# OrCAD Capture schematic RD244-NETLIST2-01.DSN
size A3
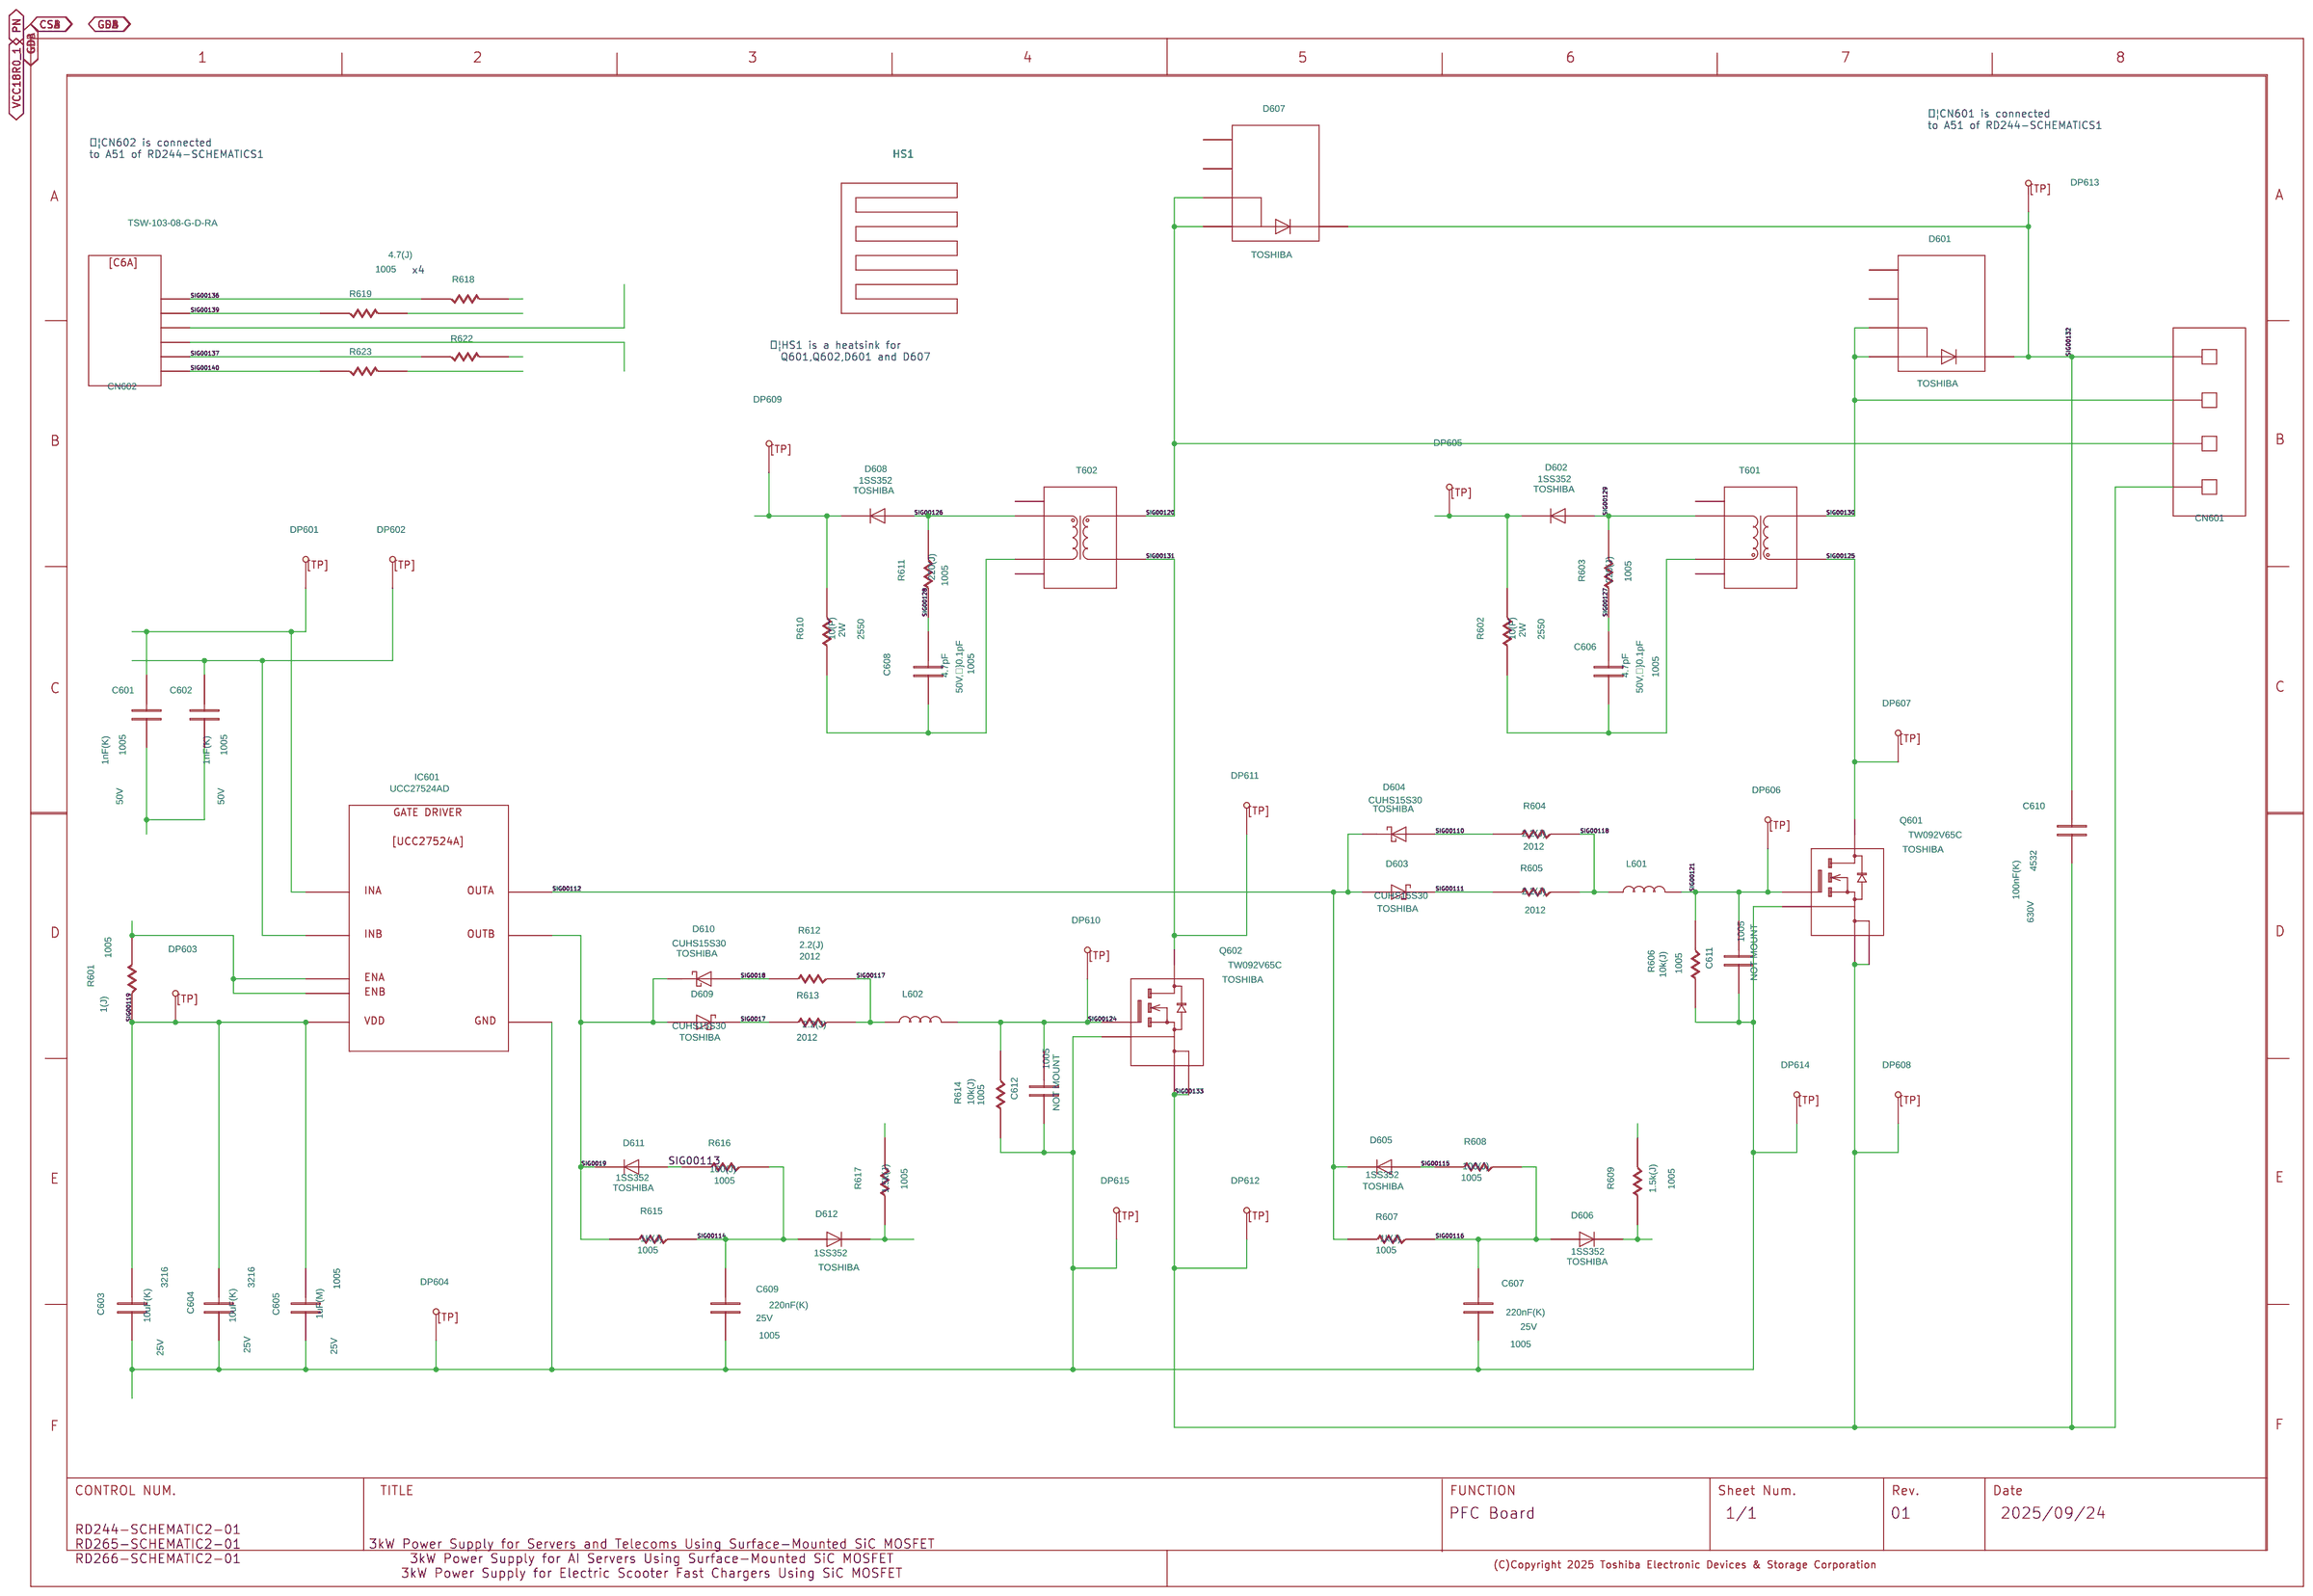
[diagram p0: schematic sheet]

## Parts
C601  C
C602  C
C603  C
C604  C
C605  C
C606  C
C607  C
C608  C
C609  C
C610  C
C611  C
C612  C
CN601  RD-244_CN_FROM_PFC
CN602  C6A
D601  TRS12V65H
D602  D
D603  CUHS15S30
D604  CUHS15S30
D605  D
D606  D
D607  TRS12V65H
D608  D
D609  CUHS15S30
D610  CUHS15S30
D611  D
D612  D
DP601  TP
DP602  TP
DP603  TP
DP604  TP
DP605  TP
DP606  TP
DP607  TP
DP608  TP
DP609  TP
DP610  TP
DP611  TP
DP612  TP
DP613  TP
DP614  TP
DP615  TP
HS1  UB4060-12BM-1GG
IC601  L27524
L601  L
L602  L
Q601  NCHMOSFET_DFN8X8-02
Q602  NCHMOSFET_DFN8X8-02
R601  R
R602  R
R603  R
R604  R
R605  R
R606  R
R607  R
R608  R
R609  R
R610  R
R611  R
R612  R
R613  R
R614  R
R615  R
R616  R
R617  R
R618  R
R619  R
R622  R
R623  R
T601  PH9505_100NLT
T602  PH9505_100NLT
U?#1  WAKU_DEF100

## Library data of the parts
C601 C602 = C: CHIPSIZE: 1005; COMP: PRT_52; COMPONENTTYPE: 4; GCOUNT: 1; MAXGCOUNT: 1; SAVECOUNT: 0; SIZECODESMD: 1005; VAL1: 1nF(K); VAL2: 50V; VAL3: GRM155R71H102KA01
C603 C604 = C: CHIPSIZE: 3216; COMP: PRT_46; COMPONENTTYPE: 4; GCOUNT: 1; MAXGCOUNT: 1; SAVECOUNT: 0; SIZECODESMD: 3216; VAL1: 10uF(K); VAL2: 25V; VAL3: GRM31CR71E106KA12
C605 = C: CHIPSIZE: 1005; COMP: PRT_52; COMPONENTTYPE: 4; GCOUNT: 1; MAXGCOUNT: 1; SAVECOUNT: 0; SIZECODESMD: 1005; VAL1: 1uF(M); VAL2: 25V; VAL3: GRM155C81E105ME11
C606 C608 = C: CHIPSIZE: 1005; COMP: PRT_52; COMPONENTTYPE: 4; GCOUNT: 1; MAXGCOUNT: 1; SAVECOUNT: 0; SIZECODESMD: 1005; VAL1: 4.7pF; VAL2: 50V,}0.1pF; VAL3: GRM1555C1H4R7BA01D
C607 = C: CHIPSIZE: 1005; COMP: PRT_52; COMPONENTTYPE: 4; GCOUNT: 1; MAXGCOUNT: 1; SAVECOUNT: 0; SIZECODESMD: 1005; VAL1: 220nF(K); VAL2: 25V; VAL3: GRM155C81E224KE01
C609 = C: ADSCNVFLAG: ON; ADSCOMPONENTNAME: C_1005; CHIPSIZE: 1005; COMP: PRT_52; COMPONENTTYPE: 4; GCOUNT: 1; ICX_PART_MODEL: CON_47N; MAXGCOUNT: 1; SAVECOUNT: 0; SIZECODESMD: 1005; SQ_PART_MODEL: CON_47N; VAL1: 220nF(K); VAL2: 25V; VAL3: GRM155C81E224KE01
C610 = C: ADSCNVFLAG: ON; ADSCOMPONENTNAME: C_4532; COMP: K03S007Y; COMPONENTTYPE: 4; GCOUNT: 1; ICX_PART_MODEL: CON_100N; MAXGCOUNT: 1; SAVECOUNT: 0; SIZECODESMD: 4532; SQ_PART_MODEL: CON_100N; VAL1: 100nF(K); VAL2: 630V; VAL3: GRJ43DR72J104KWJ1K
C611 C612 = C: CHIPSIZE: 1005; COMP: PRT_52; COMPONENTTYPE: 4; GCOUNT: 1; MAXGCOUNT: 1; NOTMOUNT: NOT MOUNT; SAVECOUNT: 0; SIZECODESMD: 1005; VAL1: 1uF(M); VAL2: 25V; VAL3: GRM155C81E105ME11
CN601 = RD-244_CN_FROM_PFC: COMPONENTTYPE: 4
CN602 = C6A: ADSCNVFLAG: ON; COMP: K22S0030; COMPONENTTYPE: 4; GATENO: 1; GCOUNT: 1; MAXGCOUNT: 1; OUMEPARTTYPE2: CN; VAL3: TSW-103-08-G-D-RA
D601 D607 = TRS12V65H: COMPONENTTYPE: 4; GCOUNT: 1; MAXGCOUNT: 1; USERCOMPTEXT3: TOSHIBA
D602 D605 D606 D608 D611 = D: COMP: PRT_27; COMPONENTTYPE: 4; GCOUNT: 1; MAXGCOUNT: 1; USERCOMPTEXT2: 80V,0.1A; USERCOMPTEXT3: TOSHIBA; VAL1: 1SS352(TPH3,F); VAL3: 1SS352
D603 D604 D609 D610 = CUHS15S30: COMPONENTTYPE: 4; GCOUNT: 1; MAXGCOUNT: 1; USERCOMPTEXT2: 30V,1.5A; USERCOMPTEXT3: TOSHIBA
D612 = D: ADSCNVFLAG: ON; ADSCOMPONENTNAME: D_D; COMP: PRT_27; COMPONENTTYPE: 4; GCOUNT: 1; MAXGCOUNT: 1; USERCOMPTEXT2: 80V,0.1A; USERCOMPTEXT3: TOSHIBA; VAL1: 1SS352(TPH3,F); VAL3: 1SS352
DP601-DP615 = TP: COMP: DTP815; COMPONENTTYPE: 4; USERCOMPTEXT1: ƒ³1.5mm
HS1 = UB4060-12BM-1GG: COMPONENTTYPE: 4
IC601 = L27524: COMP: PRT_63; COMPONENTTYPE: 4; VAL3: UCC27524AD
L601 L602 = L: COMP: PRT_30; COMPONENTTYPE: 4; SAVECOUNT: 0; VAL3: LSMCC321611T800RG
Q601 Q602 = NCHMOSFET_DFN8X8-02: COMPONENTTYPE: 4; USERCOMPTEXT3: TOSHIBA; VAL3: TW092V65C
R601 = R: CHIPSIZE: 1608; COMP: GDM010004481; COMPONENTTYPE: 4; GCOUNT: 1; MAXGCOUNT: 1; SAVECOUNT: 0; SIZECODESMD: 1005; VAL1: 1(J); VAL2: 63mW; VAL3: RK73B1ETTP1R0J
R602 R610 = R: ADSCNVFLAG: ON; ADSCOMPONENTNAME: R_2550; COMP: K01S003U; COMPONENTTYPE: 4; GCOUNT: 1; ICX_PART_MODEL: RES_750; MAXGCOUNT: 1; SAVECOUNT: 0; SIZECODESMD: 2550; SQ_PART_MODEL: RES_750; USERCOMPTEXT1: 10(F); VAL1: 10(F); VAL2: 2W; VAL3: WK73R2H2TTE7500F
R603 R611 = R: CHIPSIZE: 1608; COMP: GDM010004481; COMPONENTTYPE: 4; GCOUNT: 1; MAXGCOUNT: 1; SAVECOUNT: 0; SIZECODESMD: 1005; VAL1: 220(J); VAL2: 63mW; VAL3: RK73B1ETTP221J
R604 R605 R612 R613 = R: CHIPSIZE: 3216; COMP: R2012; COMPONENTTYPE: 4; GCOUNT: 1; MAXGCOUNT: 1; SAVECOUNT: 0; SIZECODESMD: 2012; VAL1: 2.2(J); VAL2: 250mW; VAL3: RK73B2ATTD2R2J
R606 R614 = R: CHIPSIZE: 1608; COMP: GDM010004481; COMPONENTTYPE: 4; GCOUNT: 1; MAXGCOUNT: 1; SAVECOUNT: 0; SIZECODESMD: 1005; VAL1: 10k(J); VAL2: 63mW; VAL3: RK73B1ETTP103J
R607 = R: ADSCNVFLAG: ON; ADSCOMPONENTNAME: R_1608; CHIPSIZE: 1608; COMP: GDM010004481; COMPONENTTYPE: 4; GCOUNT: 1; ICX_PART_MODEL: RES_1.74K; MAXGCOUNT: 1; SAVECOUNT: 0; SIZECODESMD: 1005; SQ_PART_MODEL: RES_1.74K; VAL1: 1k(J); VAL2: 63mW; VAL3: RK73B1ETTP102J
R608 R616 = R: CHIPSIZE: 1608; COMP: GDM010004481; COMPONENTTYPE: 4; GCOUNT: 1; MAXGCOUNT: 1; SAVECOUNT: 0; SIZECODESMD: 1005; VAL1: 100(J); VAL2: 63mW; VAL3: RK73B1ETTP101J
R609 R617 = R: CHIPSIZE: 1608; COMP: GDM010004481; COMPONENTTYPE: 4; GCOUNT: 1; MAXGCOUNT: 1; SAVECOUNT: 0; SIZECODESMD: 1005; VAL1: 1.5k(J); VAL2: 63mW; VAL3: RK73B1ETTP152J
R615 = R: CHIPSIZE: 1608; COMP: GDM010004481; COMPONENTTYPE: 4; GCOUNT: 1; MAXGCOUNT: 1; SAVECOUNT: 0; SIZECODESMD: 1005; VAL1: 1K(J); VAL2: 63mW; VAL3: RK73B1ETTP102J
R618 = R: CHIPSIZE: 1608; COMP: GDM010004481; COMPONENTTYPE: 4; GCOUNT: 1; MAXGCOUNT: 1; SAVECOUNT: 0; SIZECODESMD: 1005; VAL1: 4.7(J); VAL2: 63mW; VAL3: RK73B1ETTP4R7J
R619 = R: CHIPSIZE: 1608; COMP: GDM010004481; COMPONENTTYPE: 4; GCOUNT: 1; MAXGCOUNT: 1; SAVECOUNT: 0; SIZECODESMD: 1005; VAL1: 4.7; VAL2: 63mW; VAL3: RK73B1ETTP4R7J
R622 R623 = R: CHIPSIZE: 1608; COMP: GDM010004481; COMPONENTTYPE: 4; GCOUNT: 1; MAXGCOUNT: 1; SAVECOUNT: 0; SIZECODESMD: 1005; VAL1: 0; VAL2: 63mW; VAL3: RK73Z1ETTP
T601 T602 = PH9505_100NLT: COMPONENTTYPE: 4; GCOUNT: 1; MAXGCOUNT: 1
U?#1 = WAKU_DEF100: COMPONENTTYPE: 2; DATE: 2025/09/24; DESIGNED: TOSHIBA; DRAWINGNUMBER: RD244-SCHEMATIC2-01 / RD265-SCHEMATIC2-01 / RD266-SCHEMATIC2-01; FUNCTION: PFC Board; PAGENUMBER: 2; REVISION: 01; SAVECOUNT: 3; SHEETNUMBER: 1/1; SHTSAVECOUNT: 186; TITLE: 3kW Power Supply for Servers and Telecoms Using Surface-Mounted SiC MOSFET / 3kW Power Supply for AI Servers Using Surface-Mounted SiC MOSFET / 3kW Power Supply for Electric Scooter Fast Chargers Using SiC MOSFET; UPDATEDATE: 2025.9.24; UPDATETIME: 20:29:13

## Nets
VCC18R0_1: CN602.3 IC601.1 IC601.8 R601.1 R609.2 R617.2
CSA: D602.C D606.C DP605.1 R602.2 R609.1 R623.1
CSB: D608.C D612.C DP609.1 R610.2 R617.1 R622.1
GDA: C601.2 DP601.1 IC601.2 R618.1
GDB: C602.2 DP602.1 IC601.4 R619.1
PN: C601.1 C602.1 C603.1 C604.1 C605.1 C606.1 C607.1 C608.1 C609.1 C611.1 C612.1 CN602.4 DP604.1 DP614.1 DP615.1 IC601.3 Q601.2 Q602.2 R602.1 R606.1 R610.1 R614.1 T601.5 T602.4
SIG0017: D609.C R613.1
SIG0018: D610.A R612.1
SIG0019: D609.A D610.C D611.C IC601.5 R615.1
SIG00110: D604.A R604.1
SIG00111: D603.C R605.1
SIG00112: D603.A D604.C D605.C IC601.7 R607.1
SIG00113: D611.A R616.1
SIG00114: C609.2 D612.A R615.2 R616.2
SIG00115: D605.A R608.1
SIG00116: C607.2 D606.A R607.2 R608.2
SIG00117: L602.1 R612.2 R613.2
SIG00118: L601.1 R604.2 R605.2
SIG00119: C603.2 C604.2 C605.2 DP603.1 IC601.6 R601.2
SIG00120: CN601.3 D607.3 D607.4 T602.1
SIG00121: C611.2 DP606.1 L601.2 Q601.1 R606.2
SIG00124: C612.2 DP610.1 L602.2 Q602.1 R614.2
SIG00125: DP607.1 Q601.5 T601.1
SIG00126: D608.A R611.2 T602.5
SIG00127: C606.2 R603.1
SIG00128: C608.2 R611.1
SIG00129: D602.A R603.2 T601.4
SIG00130: CN601.2 D601.3 D601.4 T601.2
SIG00131: DP611.1 Q602.5 T602.2
SIG00132: C610.2 CN601.1 D601.5 D607.5 DP613.1
SIG00133: C610.1 CN601.4 DP608.1 DP612.1 Q601.3 Q601.4 Q602.3 Q602.4
SIG00136: CN602.1 R618.2
SIG00137: CN602.5 R622.2
SIG00139: CN602.2 R619.2
SIG00140: CN602.6 R623.2

Not connected (* = marked no-connect by the designer): D601 1 2; D607 1 2; T601 3 6; T602 3 6

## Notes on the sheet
- ¦CN601 is connected
  to A51 of RD244-SCHEMATICS1
- ¦CN602 is connected
  to A51 of RD244-SCHEMATICS1
- x4
- ¦HS1 is a heatsink for
    Q601,Q602,D601 and D607
